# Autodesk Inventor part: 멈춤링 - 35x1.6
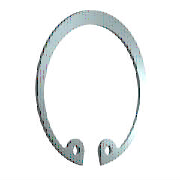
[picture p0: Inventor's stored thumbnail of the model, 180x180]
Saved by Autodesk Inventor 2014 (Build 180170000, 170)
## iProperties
IsCustomPart: 1
Created: 2015-09
Part Number: 멈춤링 - 35x1.6
Material: 강철, 연강
Description: 리테이닝 링(C형)
Document SubType Name: Modeling
Standard: KS B 1336
Designer: mduedu
Standards Organization: KS
Language: ko-KR
Size Designation: 35x1.6
Categories: <MemberInstance><Categories><Category DisplayName="샤프트 부품" InternalName="7f7aeb1f-a693-4053-b835-cee3144e0d98" Mnemonic="SHFT"><Category DisplayName="써클립" Inter
Density: 7.86 g/cm^3
Mass: 3.5371 g
Surface Area: 9.09651 cm^2
Volume: 0.450013 cm^3
Appearance: 광택 - 검은색
Author: mduedu
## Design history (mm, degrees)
sketch "스케치1"
  geometry: L1 (0, 15.113)-(0, -73.177) reference; L2 (-45.5, 0)-(45.5, 0) reference; L3 (-4.964, 1)-(1.502, 1); L4 (0, -2.5)-(-5.307, -2.5); L5 (0, -17.5)-(-8.583, -33.888); L6 (-8.583, -33.888)-(-21.772, -26.981); L7 (-7.377, -31.585)-(-17.631, -26.214); L8 (-5.162, -32.745)-(-6.29, -34.898); L9 (5.162, -32.745)-(6.29, -34.898); C1 r 1.25 at (-7.377, -31.585); C2 r 1.25 at (7.377, -31.585); A1 r 15.875 centre (0, -18.375) between (11.82, -28.972) and (-11.82, -28.972); A2 r 18.5 centre (0, -17.5) between (6.29, -34.898) and (-6.29, -34.898); A3 r 2.5 centre (-7.377, -31.585) between (-5.162, -32.745) and (-8.668, -29.444); A4 r 2.5 centre (-9.959, -27.303) between (-11.82, -28.972) and (-8.668, -29.444); A5 r 2.5 centre (9.959, -27.303) between (8.668, -29.444) and (11.82, -28.972); A6 r 2.5 centre (7.377, -31.585) between (8.668, -29.444) and (5.162, -32.745); 3 further points
  constraints: 15 point on circle, 14 end point, 9 symmetric about line, 8 centre point, 6 tangent, 4 coincident, 4 point on line, 3 perpendicular, 1 parallel, 4 other
  dimensions: "d8" = 0.875 distance of A1.centre L5.start (= 0.25 x SRB1); "d38" = 3.5 distance between parallel lines of L4 L3 (= SRB1); "d39" = 17.5 distance from line of L5.start L2 (= 0.5 x WD); "d43" = 18.5 radius of A2 (= 0.5 x ND); "d45" = 2.6 distance between parallel lines of L7 L6 (= 0.5 x SRB2); "d46" = 2.5 radius of A4 (= SD5); "d47" = 6.29 distance from line of L1 L8.end (= 0.17 x ND); "d48" = 2.5 diameter of C1 (= SD5); "d49" = 2.5 radius of A3 (= SD5)
extrude "본체" new body sketch "스케치1" distance "d2" = 1.6 (= SD); taper "d3" = 0 deg
workaxis "Work Axis1"
workaxis "Work Axis2"
workplane "Work Plane1"
body "Solid1"
other parameters: "WD" = 35 [user parameter; used in 3 equation terms], "SD" = 1.6 [user parameter; used in 1 equation term], "SRB1" = 3.5 [user parameter; used in 2 equation terms], "ND" = 37 [user parameter; used in 2 equation terms], "SRB2" = 5.2 [user parameter; used in 1 equation term], "SD5" = 2.5 [user parameter; used in 3 equation terms], "d50" = 0, "d51" = 0, "d52" = 0, "d53" = 0, "WDMIN" = 34 [user parameter], "SD6" = 37.8 [user parameter], "WDMAX" = 35 (= WD) [user parameter], "NND" = 35 (= WD) [user parameter]
